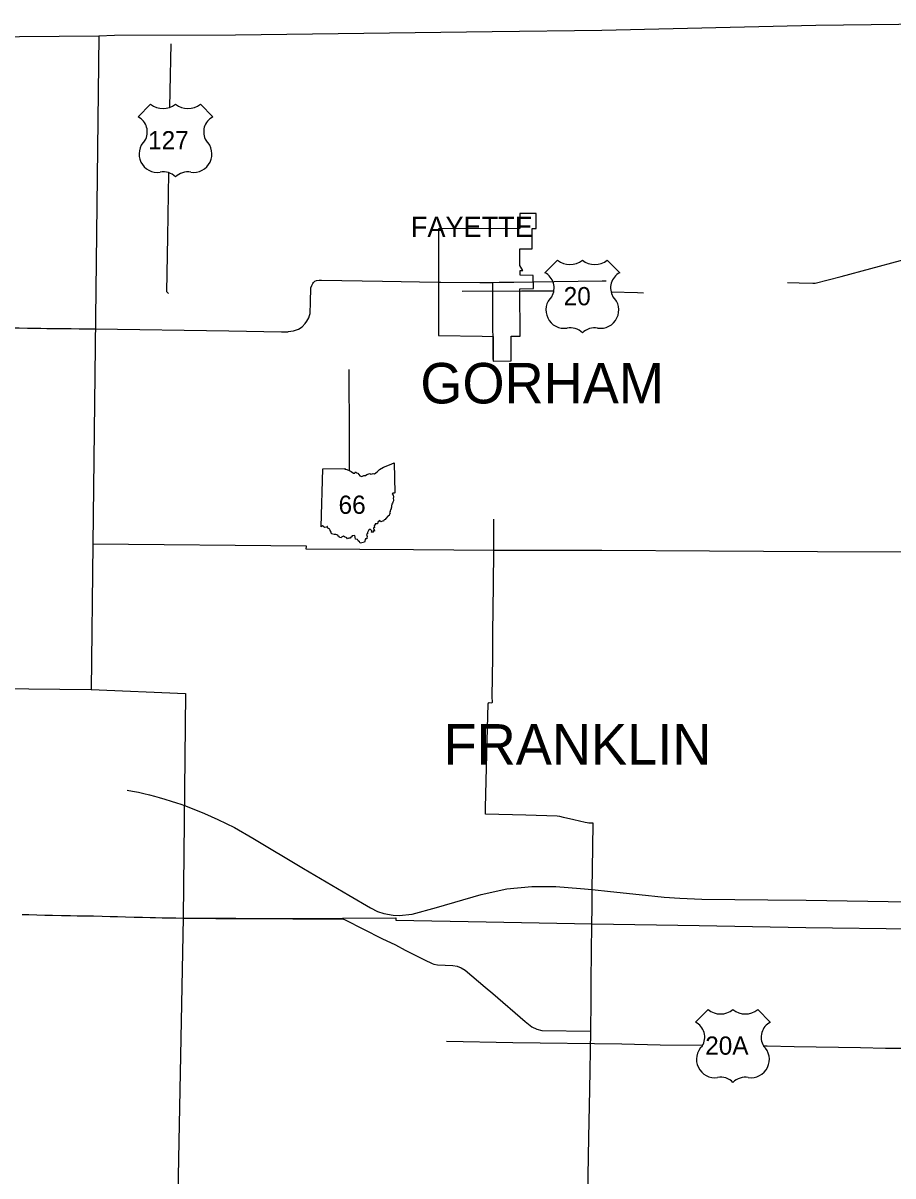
# Model space of a CAD drawing. Extents: x -232 to 448, y 619 to 1059.
# Drawn here: x -70 to -26, y 896.5 to 955 of the extents above; entities that cross this region are included whole.
import ezdxf

# ---------------------------------------------------------------- set-up
doc = ezdxf.new("R2010")
doc.units = 0
doc.layers.add('Default', color=7, linetype='Continuous')

msp = doc.modelspace()

# ---------------------------------------------------------------- linework, layer by layer
at = {"layer": 'Default'}
for p, q in [((-63.586, 950.862), (-64.221, 950.227)), ((-63.586, 950.862), (-64.221, 950.227)), ((-60.431, 950.227), (-61.066, 950.862)), ((-60.431, 950.227), (-61.066, 950.862)), ((-44.043, 945.329), (-44.87, 945.329)), ((-44.87, 945.329), (-44.87, 944.56)), ((-44.043, 944.567), (-44.043, 945.329)), ((-49.001, 944.547), (-49.001, 939.142)), ((-44.256, 944.565), (-44.043, 944.567)), ((-44.256, 943.835), (-44.256, 944.565)), ((-44.877, 943.532), (-44.256, 943.532)), ((-44.256, 943.532), (-44.256, 943.835)), ((-42.969, 942.956), (-43.603, 942.322)), ((-42.969, 942.956), (-43.603, 942.322)), ((-39.814, 942.322), (-40.448, 942.956)), ((-39.814, 942.322), (-40.448, 942.956)), ((-44.718, 942.431), (-44.883, 942.683)), ((-44.865, 942.431), (-44.718, 942.431)), ((-45.315, 937.851), (-45.323, 939.099)), ((-46.222, 937.846), (-45.315, 937.851)), ((-54.944, 929.447), (-54.862, 932.376)), ((-54.944, 929.447), (-54.862, 932.376)), ((-83.673, 921.377), (-66.605, 921.202)), ((-35.338, 904.963), (-35.972, 904.329)), ((-35.338, 904.963), (-35.972, 904.329)), ((-32.183, 904.329), (-32.817, 904.963)), ((-32.183, 904.329), (-32.817, 904.963))]:
    msp.add_line(p, q, dxfattribs=at)
for points in [[(-66.216, 954.34), (-65.408, 954.364), (-59.285, 954.386), (-46.284, 954.55), (-40.715, 954.621), (-29.877, 954.878), (-24.273, 954.939), (-18.844, 954.953), (-16.282, 954.98)], [(-87.688, 954.093), (-82.272, 954.171), (-76.931, 954.252), (-74.267, 954.263), (-66.216, 954.34)], [(-66.216, 954.34), (-66.519, 928.567)], [(-62.609, 950.704), (-62.595, 951.532), (-62.543, 953.92)], [(-62.675, 941.268), (-62.769, 941.353), (-62.716, 944.147), (-62.663, 947.393)], [(-44.87, 944.56), (-49.001, 944.547)], [(-44.883, 942.683), (-44.877, 943.532)], [(-30.721, 941.808), (-30.029, 941.792), (-29.914, 941.797), (-28.59, 942.139), (-25.583, 942.938), (-25.462, 942.971)], [(-44.867, 939.102), (-44.868, 941.504), (-44.177, 941.518), (-44.194, 942.187), (-44.865, 942.199), (-44.865, 942.431)], [(-55.531, 940.153), (-55.504, 940.251), (-55.484, 940.826), (-55.469, 941.56), (-55.424, 941.676), (-55.373, 941.785)], [(-55.373, 941.785), (-55.331, 941.827), (-55.265, 941.887), (-55.18, 941.927), (-55.048, 941.942), (-54.934, 941.94)], [(-54.934, 941.94), (-51.834, 941.894), (-49.016, 941.849)], [(-49.016, 941.849), (-48.875, 941.847), (-46.902, 941.822), (-46.631, 941.826)], [(-46.631, 941.826), (-46.25, 941.831), (-45.925, 941.836)], [(-46.249, 941.668), (-46.25, 941.831)], [(-46.248, 941.343), (-46.249, 941.668)], [(-45.925, 941.836), (-45.183, 941.848), (-44.188, 941.86)], [(-44.188, 941.86), (-43.139, 941.872), (-40.712, 941.907), (-40.5, 941.908)], [(-31.311, 941.821), (-30.721, 941.808)], [(-47.801, 941.392), (-44.795, 941.408), (-43.15, 941.413)], [(-46.235, 939.122), (-46.237, 939.387), (-46.248, 941.343)], [(-40.256, 941.356), (-38.918, 941.312), (-38.613, 941.305)], [(-56.604, 939.335), (-56.476, 939.361), (-56.338, 939.382), (-56.093, 939.459), (-55.898, 939.58), (-55.753, 939.744), (-55.672, 939.859), (-55.57, 940.043), (-55.531, 940.153)], [(-74.417, 939.583), (-74.347, 939.582), (-74.045, 939.577), (-73.667, 939.567), (-73.327, 939.561), (-73.033, 939.556), (-72.757, 939.552), (-72.393, 939.549), (-72.056, 939.547), (-71.739, 939.544), (-71.426, 939.54), (-71.006, 939.534), (-70.624, 939.526), (-70.243, 939.525), (-69.828, 939.519), (-69.453, 939.513), (-69.142, 939.51), (-68.846, 939.503), (-68.515, 939.501), (-68.225, 939.503)], [(-68.225, 939.503), (-67.961, 939.499), (-67.618, 939.493), (-67.213, 939.486), (-66.793, 939.482), (-66.39, 939.486)], [(-66.39, 939.486), (-59.627, 939.374), (-56.95, 939.318), (-56.625, 939.331), (-56.604, 939.335)], [(-49.001, 939.142), (-46.783, 939.103), (-46.234, 939.09), (-46.222, 937.846)], [(-46.223, 937.932), (-46.235, 939.122)], [(-45.323, 939.099), (-44.867, 939.102)], [(-53.504, 932.282), (-53.505, 933.136), (-53.509, 934.436), (-53.52, 936.949), (-53.525, 937.415)], [(-54.862, 932.376), (-53.726, 932.395), (-53.744, 932.359), (-53.637, 932.352), (-53.523, 932.289), (-53.426, 932.25), (-53.309, 932.157), (-53.238, 932.158), (-53.208, 932.234), (-53.154, 932.175), (-53.09, 932.165), (-52.979, 932.025), (-52.888, 931.994), (-52.778, 932.042), (-52.696, 932.05), (-52.637, 932.098), (-52.481, 932.138), (-52.437, 932.114), (-52.355, 932.119), (-52.313, 932.137), (-52.241, 932.121), (-52.114, 932.227), (-51.984, 932.353), (-51.783, 932.471), (-51.483, 932.583), (-51.246, 932.684), (-51.212, 931.164)], [(-54.862, 932.376), (-53.726, 932.395), (-53.744, 932.359), (-53.637, 932.352), (-53.523, 932.289), (-53.426, 932.25), (-53.309, 932.157), (-53.238, 932.158), (-53.208, 932.234), (-53.154, 932.175), (-53.09, 932.165), (-52.979, 932.025), (-52.888, 931.994), (-52.778, 932.042), (-52.696, 932.05), (-52.637, 932.098), (-52.481, 932.138), (-52.437, 932.114), (-52.355, 932.119), (-52.313, 932.137), (-52.241, 932.121), (-52.114, 932.227), (-51.984, 932.353), (-51.783, 932.471), (-51.483, 932.583), (-51.246, 932.684), (-51.212, 931.164)], [(-51.212, 931.164), (-51.247, 931.143), (-51.302, 931.153), (-51.338, 931.11), (-51.293, 931.039), (-51.271, 930.964), (-51.29, 930.881), (-51.272, 930.813), (-51.284, 930.755), (-51.319, 930.699), (-51.331, 930.644), (-51.36, 930.587), (-51.357, 930.555), (-51.385, 930.53), (-51.38, 930.435), (-51.394, 930.382), (-51.389, 930.337), (-51.434, 930.325), (-51.424, 930.287), (-51.452, 930.258), (-51.446, 930.208), (-51.479, 930.176), (-51.447, 930.113), (-51.473, 930.092), (-51.493, 930.015), (-51.551, 929.999), (-51.667, 929.857), (-51.708, 929.804), (-51.753, 929.79), (-51.779, 929.735), (-51.835, 929.735), (-51.92, 929.697), (-51.976, 929.763), (-52.072, 929.684), (-52.083, 929.592), (-52.206, 929.595), (-52.201, 929.549), (-52.228, 929.535), (-52.253, 929.489), (-52.239, 929.407), (-52.296, 929.386), (-52.289, 929.338), (-52.252, 929.309), (-52.236, 929.218), (-52.297, 929.236), (-52.347, 929.16), (-52.398, 929.178), (-52.381, 929.243), (-52.468, 929.321), (-52.55, 929.258), (-52.592, 929.158), (-52.593, 929.091), (-52.654, 929.05), (-52.615, 928.955), (-52.622, 928.889), (-52.621, 928.827), (-52.697, 928.829), (-52.743, 928.661)], [(-51.212, 931.164), (-51.247, 931.143), (-51.302, 931.153), (-51.338, 931.11), (-51.293, 931.039), (-51.271, 930.964), (-51.29, 930.881), (-51.272, 930.813), (-51.284, 930.755), (-51.319, 930.699), (-51.331, 930.644), (-51.36, 930.587), (-51.357, 930.555), (-51.385, 930.53), (-51.38, 930.435), (-51.394, 930.382), (-51.389, 930.337), (-51.434, 930.325), (-51.424, 930.287), (-51.452, 930.258), (-51.446, 930.208), (-51.479, 930.176), (-51.447, 930.113), (-51.473, 930.092), (-51.493, 930.015), (-51.551, 929.999), (-51.667, 929.857), (-51.708, 929.804), (-51.753, 929.79), (-51.779, 929.735), (-51.835, 929.735), (-51.92, 929.697), (-51.976, 929.763), (-52.072, 929.684), (-52.083, 929.592), (-52.206, 929.595), (-52.201, 929.549), (-52.228, 929.535), (-52.253, 929.489), (-52.239, 929.407), (-52.296, 929.386), (-52.289, 929.338), (-52.252, 929.309), (-52.236, 929.218), (-52.297, 929.236), (-52.347, 929.16), (-52.398, 929.178), (-52.381, 929.243), (-52.468, 929.321), (-52.55, 929.258), (-52.592, 929.158), (-52.593, 929.091), (-52.654, 929.05), (-52.615, 928.955), (-52.622, 928.889), (-52.621, 928.827), (-52.697, 928.829), (-52.743, 928.661)], [(-52.743, 928.661), (-52.876, 928.629), (-52.968, 928.609), (-53, 928.686), (-53.066, 928.726), (-53.109, 928.803), (-53.203, 928.813), (-53.226, 928.919), (-53.236, 929.005), (-53.366, 928.984), (-53.401, 928.931), (-53.447, 928.917), (-53.474, 928.864), (-53.536, 928.86), (-53.603, 928.835), (-53.647, 928.887), (-53.757, 928.939), (-53.806, 928.966), (-53.91, 928.924), (-53.932, 928.875), (-54.014, 928.896), (-54.033, 928.951), (-54.083, 928.968), (-54.094, 929.026), (-54.2, 929.057), (-54.281, 929.045), (-54.425, 929.092), (-54.434, 929.169), (-54.482, 929.262), (-54.508, 929.327), (-54.599, 929.377), (-54.617, 929.454), (-54.646, 929.452), (-54.673, 929.42), (-54.773, 929.406), (-54.814, 929.438), (-54.87, 929.491), (-54.944, 929.447)], [(-52.743, 928.661), (-52.876, 928.629), (-52.968, 928.609), (-53, 928.686), (-53.066, 928.726), (-53.109, 928.803), (-53.203, 928.813), (-53.226, 928.919), (-53.236, 929.005), (-53.366, 928.984), (-53.401, 928.931), (-53.447, 928.917), (-53.474, 928.864), (-53.536, 928.86), (-53.603, 928.835), (-53.647, 928.887), (-53.757, 928.939), (-53.806, 928.966), (-53.91, 928.924), (-53.932, 928.875), (-54.014, 928.896), (-54.033, 928.951), (-54.083, 928.968), (-54.094, 929.026), (-54.2, 929.057), (-54.281, 929.045), (-54.425, 929.092), (-54.434, 929.169), (-54.482, 929.262), (-54.508, 929.327), (-54.599, 929.377), (-54.617, 929.454), (-54.646, 929.452), (-54.673, 929.42), (-54.773, 929.406), (-54.814, 929.438), (-54.87, 929.491), (-54.944, 929.447)], [(-46.199, 928.637), (-46.2, 929.825)], [(-66.519, 928.567), (-66.605, 921.202)], [(-18.945, 928.163), (-29.796, 928.178), (-35.267, 928.206), (-40.728, 928.233), (-46.179, 928.243), (-50.264, 928.27), (-55.696, 928.311), (-55.686, 928.456), (-66.519, 928.567)], [(-44.566, 914.817), (-46.614, 914.879), (-46.616, 914.912), (-46.608, 915.189), (-46.537, 918.586), (-46.482, 920.464), (-46.467, 920.513), (-46.434, 920.527), (-46.289, 920.523), (-46.266, 920.548), (-46.273, 920.817), (-46.251, 922.827), (-46.24, 924.059), (-46.217, 926.491), (-46.199, 928.259), (-46.199, 928.637)], [(-66.605, 921.202), (-61.811, 920.996), (-61.94, 909.617)], [(-64.78, 916.093), (-64.497, 916.039), (-64.196, 915.984), (-63.934, 915.92), (-63.648, 915.851), (-63.392, 915.788), (-63.157, 915.724), (-62.863, 915.637), (-62.538, 915.54), (-62.281, 915.456), (-62.056, 915.374), (-61.875, 915.31)], [(-61.875, 915.31), (-61.303, 915.101), (-60.863, 914.915), (-60.179, 914.609), (-59.342, 914.194), (-58.406, 913.653), (-55.839, 912.126), (-53.54, 910.765), (-52.447, 910.12), (-52.092, 909.945), (-51.763, 909.83), (-51.288, 909.757), (-50.997, 909.733), (-50.329, 909.811), (-49.092, 910.142), (-46.83, 910.8), (-45.53, 911.095), (-44.275, 911.204), (-43.06, 911.208), (-41.795, 911.107), (-41.206, 911.061), (-40.288, 910.955), (-38.831, 910.801), (-37.57, 910.673), (-36.768, 910.608), (-35.656, 910.568), (-32.305, 910.529), (-30.368, 910.512), (-25.17, 910.436)], [(-41.152, 914.425), (-41.296, 914.42), (-41.388, 914.421), (-41.466, 914.426), (-41.566, 914.444), (-42.137, 914.58), (-42.659, 914.707), (-42.841, 914.753), (-42.987, 914.769), (-44.566, 914.817)], [(-41.216, 910.104), (-41.206, 911.061), (-41.173, 913.19), (-41.152, 914.425)], [(-41.255, 906.433), (-41.242, 907.867), (-41.225, 909.316), (-41.216, 910.104)], [(-70.098, 909.787), (-69.756, 909.783), (-69.359, 909.767), (-68.952, 909.761), (-68.555, 909.754), (-68.109, 909.743), (-67.652, 909.734), (-67.309, 909.727), (-66.854, 909.718), (-66.478, 909.711), (-66.036, 909.698), (-65.639, 909.689), (-65.271, 909.68), (-64.864, 909.67), (-64.426, 909.657), (-63.998, 909.645), (-63.614, 909.635), (-63.34, 909.631), (-62.997, 909.624), (-62.678, 909.619), (-62.31, 909.614), (-61.94, 909.609)], [(-61.94, 909.617), (-62.463, 882.554)], [(-61.94, 909.617), (-56.588, 909.577), (-51.156, 909.61), (-51.158, 909.496), (-46.578, 909.412), (-41.204, 909.315), (-35.795, 909.227), (-30.382, 909.129), (-19.544, 908.989)], [(-61.94, 909.609), (-60.277, 909.587), (-59.271, 909.587), (-58.097, 909.578), (-56.384, 909.566), (-53.975, 909.57), (-53.849, 909.565), (-53.735, 909.524), (-51.866, 908.575), (-51.177, 908.241), (-50.683, 907.982), (-49.712, 907.496), (-49.324, 907.296), (-49.24, 907.264), (-49.05, 907.235), (-48.268, 907.197), (-48.049, 907.16), (-47.853, 907.086), (-47.647, 906.958), (-46.627, 906.103), (-46.251, 905.774), (-44.61, 904.363), (-44.276, 904.096), (-44.023, 903.974), (-43.768, 903.899), (-41.285, 903.878)], [(-41.285, 903.878), (-41.265, 905.385), (-41.255, 906.433)], [(-41.385, 898.478), (-41.336, 900.899), (-41.285, 903.878)], [(-48.586, 903.362), (-45.229, 903.306), (-39.705, 903.227), (-37.764, 903.187), (-35.606, 903.161)], [(-32.533, 903.124), (-32.335, 903.121), (-30.979, 903.089), (-27.619, 903.037), (-26.341, 903.018), (-23.475, 903.003), (-22.611, 903.008), (-21.845, 903.012), (-20.215, 903.001), (-19.452, 902.999), (-18.229, 902.954), (-17.231, 902.921), (-16.409, 902.889), (-15.389, 902.882), (-13.299, 902.861), (-11.008, 902.845), (-10.315, 902.84), (-7.632, 902.823), (-5.985, 902.826)], [(-41.476, 893.037), (-41.452, 894.56), (-41.397, 897.519), (-41.385, 898.478)]]:
    msp.add_lwpolyline(points, dxfattribs=at)
for centre, radius, start, end in [((-62.956, 951.663), 1.019, 231.81301, 308.18697), ((-62.956, 951.663), 1.019, 231.81301, 308.18697), ((-61.696, 951.663), 1.019, 231.81301, 308.18697), ((-61.696, 951.663), 1.019, 231.81301, 308.18697), ((-64.617, 949.462), 0.862, 329.11751, 62.61081), ((-64.617, 949.462), 0.862, 329.11751, 62.61081), ((-60.035, 949.462), 0.862, 117.38919, 210.88249), ((-60.035, 949.462), 0.862, 117.38919, 210.88249), ((-63.243, 948.339), 0.93, 133.00455, 278.72816), ((-63.243, 948.339), 0.93, 133.00455, 278.72816), ((-61.409, 948.339), 0.93, 261.27184, 46.99545), ((-61.409, 948.339), 0.93, 261.27184, 46.99545), ((-62.93, 946.605), 0.832, 43.41772, 101.87423), ((-62.93, 946.605), 0.832, 43.41772, 101.87423), ((-61.704, 946.55), 0.883, 79.96126, 134.74679), ((-61.704, 946.55), 0.883, 79.96126, 134.74679), ((-42.339, 943.758), 1.019, 231.81301, 308.18697), ((-42.339, 943.758), 1.019, 231.81301, 308.18697), ((-41.078, 943.758), 1.019, 231.81301, 308.18697), ((-41.078, 943.758), 1.019, 231.81301, 308.18697), ((-44, 941.557), 0.862, 329.11751, 62.61081), ((-44, 941.557), 0.862, 329.11751, 62.61081), ((-39.417, 941.557), 0.862, 117.38919, 210.88249), ((-39.417, 941.557), 0.862, 117.38919, 210.88249), ((-42.625, 940.434), 0.93, 133.00455, 278.72816), ((-42.625, 940.434), 0.93, 133.00455, 278.72816), ((-40.792, 940.434), 0.93, 261.27184, 46.99545), ((-40.792, 940.434), 0.93, 261.27184, 46.99545), ((-42.313, 938.7), 0.832, 43.41772, 101.87423), ((-42.313, 938.7), 0.832, 43.41772, 101.87423), ((-41.087, 938.645), 0.883, 79.96126, 134.74679), ((-41.087, 938.645), 0.883, 79.96126, 134.74679), ((-34.708, 905.764), 1.019, 231.81301, 308.18697), ((-34.708, 905.764), 1.019, 231.81301, 308.18697), ((-33.447, 905.764), 1.019, 231.81301, 308.18697), ((-33.447, 905.764), 1.019, 231.81301, 308.18697), ((-36.369, 903.563), 0.862, 329.11751, 62.61081), ((-36.369, 903.563), 0.862, 329.11751, 62.61081), ((-31.786, 903.563), 0.862, 117.38919, 210.88249), ((-31.786, 903.563), 0.862, 117.38919, 210.88249), ((-34.994, 902.44), 0.93, 133.00455, 278.72816), ((-34.994, 902.44), 0.93, 133.00455, 278.72816), ((-33.161, 902.44), 0.93, 261.27184, 46.99545), ((-33.161, 902.44), 0.93, 261.27184, 46.99545), ((-34.682, 900.706), 0.832, 43.41772, 101.87423), ((-34.682, 900.706), 0.832, 43.41772, 101.87423), ((-33.456, 900.651), 0.883, 79.96126, 134.74679), ((-33.456, 900.651), 0.883, 79.96126, 134.74679)]:
    msp.add_arc(centre, radius, start, end, dxfattribs=at)

# ---------------------------------------------------------------- texts
for s, height, p in [('127', 0.9234, (-63.715, 948.578)), ('FAYETTE', 1.026, (-50.397, 944.138)), ('20', 0.9234, (-42.654, 940.673)), ('GORHAM', 2.052, (-49.919, 935.696)), ('66', 0.9234, (-54.062, 930.1)), ('FRANKLIN', 2.052, (-48.74, 917.386)), ('20A', 0.9234, (-35.484, 902.679))]:
    msp.add_text(s, height=height, dxfattribs=at).set_placement(p)

doc.saveas('drawing.dxf')
